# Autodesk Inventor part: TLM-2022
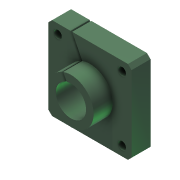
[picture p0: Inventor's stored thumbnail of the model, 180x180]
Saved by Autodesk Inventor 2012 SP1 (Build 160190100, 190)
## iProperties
Shininess: 0.0
Length Units: 11269
Angle Units: 11279
Time Units: 11290
Mass Units: 11283
Length Display Precision: 3
Angle Display Precision: 2
Compacted: True
Created: 2000-06
Part Number: TLM-2022
Description: FLANGED SUPPORT BLOCK
Vendor: REID TOOL
Document SubType Name: Modeling
Designer: Ron
Material: Aluminum-6061
Density: 2.71 g/cm^3
Density: 0.0
Volumn: 0.0
Area: 0.0
PropertySet Name: Model Information
Control State: 0
Master: False
Checked Out: False
Title: FLANGED SUPPORT BLOCK
Author: Ron
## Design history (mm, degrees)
sketch "Sketch1"
  geometry: L1 (-34.925, -34.925)-(34.925, -34.925); L2 (34.925, -34.925)-(34.925, 34.925); L3 (34.925, 34.925)-(-34.925, 34.925); L4 (-34.925, 34.925)-(-34.925, -34.925); L5 (-26.988, -26.988)-(26.988, -26.988); L6 (26.988, -26.988)-(26.988, 26.988); L7 (26.988, 26.988)-(-26.988, 26.987); L8 (-26.988, 26.987)-(-26.988, -26.988); C1 r 34.925 at (0, 0); C2 r 12.7 at (0, 0); 5 further points
  constraints: 16 end point, 6 coincident, 4 parallel, 4 tangent, 2 centre point, 2 perpendicular, 1 horizontal, 3 other
  dimensions: "d2" = 53.975 distance of L5.start L5.end; "d4" = 25.4 diameter of C2; "d16" = 69.85 distance of L2.end L3.end
node "Extrusion1" dims "d5" = 16, "d6" = 0
node "Extrusion2" dims "d8" = 16, "d9" = 0
  sketch "Sketch2"
    geometry: C1 r 12.7 at (0, 0) reference; C2 r 19.05 at (0, 0)
    constraints: 1 centre point, 1 coincident
    dimensions: "d7" = 38.1 diameter of C2
node "Extrusion3" dims "d10" = 15.748, "d11" = 0
  sketch "Sketch3"
    geometry: L1 (-34.925, 34.925)-(34.925, 34.925) reference; L2 (3.645, 12.166)-(14.982, 34.925); L3 (14.982, 34.925)-(16.322, 34.925); L4 (16.322, 34.925)-(4.786, 11.764); A1 r 12.7 centre (0, 0) between (3.645, 12.166) and (4.786, 11.764) reference
    constraints: 6 end point, 2 point on circle, 2 point on line, 1 parallel
    dimensions: "d17" = 1.2 distance between parallel lines of L4 L2
node "Chamfer1" dims "d12" = 3, "d13" = 3, "d15" = 45 deg
workaxis "Work Axis1"
workplane "Work Plane1"
hole "Hole1" sketch "Sketch1" diameter "d18" = 6.6; stored, may be unused: countersink angle "d22" = 90 deg, drill point angle "d24" = 118 deg; dims "d19" = 6, "d20" = 4, "d21" = 2, "d23" = 6.85
body "Solid1"
other parameters: "d14" = 0
